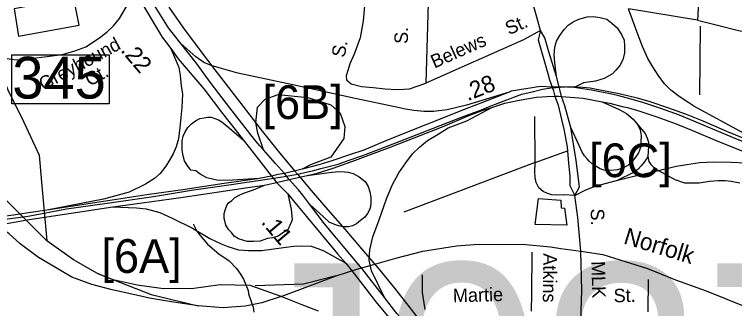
# Model space of a CAD drawing. Extents: x 1551653 to 1702041, y 811336 to 920032.
# Drawn here: x 1634519 to 1638018, y 854755 to 856187 of the extents above; entities that cross this region are included whole.
import ezdxf

# ---------------------------------------------------------------- set-up
doc = ezdxf.new("R2010")
doc.units = 0
for name, color, linetype in [('Old_Level_10', 7, 'Continuous'), ('Old_Level_11', 7, 'Continuous'), ('Old_Level_14', 7, 'Continuous'), ('Old_Level_17', 7, 'Continuous'), ('Old_Level_27', 7, 'Continuous'), ('Old_Level_28', 7, 'Continuous'), ('Old_Level_3', 7, 'Continuous'), ('Old_Level_31', 7, 'Continuous'), ('Old_Level_32', 7, 'Continuous'), ('Old_Level_35', 7, 'Continuous'), ('Old_Level_4', 7, 'Continuous'), ('Old_Level_41', 7, 'Continuous'), ('Old_Level_44', 7, 'Continuous'), ('Old_Level_47', 7, 'Continuous'), ('Old_Level_5', 7, 'Continuous'), ('Old_Level_50', 7, 'Continuous'), ('Old_Level_62', 7, 'Continuous')]:
    doc.layers.add(name, color=color, linetype=linetype)

msp = doc.modelspace()

# ---------------------------------------------------------------- linework, layer by layer
at = {"layer": 'Old_Level_27'}
for p, q in [((1637165.81, 855834.049), (1637132.268, 855832.239)), ((1637238.14, 855829.955), (1637165.81, 855834.049)), ((1635916.459, 855433.746), (1635831.443, 855412.301)), ((1635768.037, 855399.747), (1635708.82, 855387.841)), ((1635854.647, 855383.45), (1635942.198, 855402.482)), ((1635734.799, 855355.584), (1635793.039, 855369.066)), ((1635793.039, 855369.066), (1635854.647, 855383.45)), ((1634581.78, 855186.548), (1634996.937, 855249.62)), ((1634431.655, 855159.838), (1634581.78, 855186.548))]:
    msp.add_line(p, q, dxfattribs=at)
for points in [[(1637132.268, 855832.239), (1637075.639, 855836.199), (1636932.998, 855812.489), (1636922.245, 855808.742)], [(1638365.974, 855464.633), (1638214.741, 855507.081), (1638031.657, 855578.433), (1637750.359, 855695.757), (1637659.078, 855728.666), (1637571.765, 855757.86), (1637509.269, 855776.165), (1637455.868, 855789.561), (1637421.443, 855798.196), (1637322.164, 855817.451), (1637238.14, 855829.955)], [(1636922.245, 855808.742), (1636785.62, 855755.117), (1636716.75, 855727.875), (1636335.154, 855575.842), (1636216.613, 855525.784), (1636146.503, 855502.4), (1636061.359, 855474.024), (1635998.272, 855454.385), (1635916.459, 855433.746)], [(1636839.087, 855734.036), (1636902.275, 855755.117), (1636963.818, 855767.67), (1637008.634, 855775.143), (1637056.118, 855783.277), (1637105.735, 855787.6), (1637145.165, 855789.226)], [(1637145.165, 855789.226), (1637164.011, 855787.899), (1637177.001, 855787.67)], [(1637177.001, 855787.67), (1637283.064, 855778.84), (1637374.26, 855761.325)], [(1637374.26, 855761.325), (1637411.653, 855754.143), (1637471.911, 855739.026), (1637497.437, 855732.624), (1637558.267, 855714.807), (1637644.274, 855686.049), (1637734.161, 855653.643), (1637813.351, 855621.247), (1637928.857, 855572.058), (1638060.916, 855518.691), (1638279.006, 855441.845), (1638350.679, 855418.824)], [(1635942.198, 855402.482), (1635989.698, 855413.729), (1636066.967, 855438.954), (1636176.318, 855476.83), (1636249.219, 855504.885), (1636348.756, 855542.76), (1636602.803, 855640.615), (1636724.052, 855693.495), (1636792.102, 855719.441), (1636839.087, 855734.036)], [(1635831.443, 855412.301), (1635799.993, 855406.831), (1635768.037, 855399.747)], [(1635708.82, 855387.841), (1635700.182, 855386.291), (1635526.661, 855361.801), (1635348.615, 855335.148), (1635162.158, 855308.495), (1634910.501, 855269.501), (1634676.155, 855234.318)], [(1634996.937, 855249.62), (1635139.727, 855269.218), (1635327.586, 855295.87), (1635652.835, 855343.565), (1635734.799, 855355.584)], [(1634676.155, 855234.318), (1634587.23, 855220.967), (1634547.706, 855213.758)], [(1634547.706, 855213.758), (1634515.514, 855210.281), (1634403.045, 855195.464)]]:
    msp.add_lwpolyline(points, dxfattribs=at)
at = {"layer": 'Old_Level_28'}
for p, q in [((1635793.039, 855369.066), (1635846.931, 855313.314)), ((1636130.112, 854975.222), (1636159.335, 854936.7)), ((1636316.854, 854808.062), (1636208.296, 854948.192))]:
    msp.add_line(p, q, dxfattribs=at)
for points in [[(1635327.434, 856045.612), (1635267.763, 856121.124), (1635130.75, 856342.57)], [(1635106.73, 856298.457), (1635114.031, 856282.653), (1635237.133, 856076.332), (1635278.819, 856019.985)], [(1635278.819, 856019.985), (1635315.203, 855970.803), (1635439.02, 855824.439), (1635530.348, 855704.884), (1635591.277, 855626.938), (1635631.22, 855575.589)], [(1635729.063, 855527.112), (1635712.207, 855546.394), (1635684.985, 855577.536), (1635566.044, 855732.468), (1635475.699, 855850.735), (1635402.178, 855951.025), (1635327.434, 856045.612)], [(1635631.22, 855575.589), (1635661.057, 855537.231), (1635729.145, 855449.7), (1635768.037, 855399.747)], [(1635831.443, 855412.301), (1635786.833, 855461.024), (1635729.063, 855527.112)], [(1635768.037, 855399.747), (1635776.453, 855389.188), (1635793.039, 855369.066)], [(1635854.647, 855383.45), (1635842.095, 855398.273), (1635831.443, 855412.301)], [(1635954.152, 855261.07), (1635919.637, 855306.047), (1635899.9, 855333.433), (1635854.647, 855383.45)], [(1635846.931, 855313.314), (1635873.834, 855280.58), (1635930.361, 855213.229), (1636089.396, 855022.113), (1636130.112, 854975.222)], [(1636208.296, 854948.192), (1636026.474, 855166.828), (1635954.152, 855261.07)], [(1636159.335, 854936.7), (1636281.486, 854779.985), (1636372.807, 854670.288)], [(1636488.976, 854604.204), (1636376.318, 854731.305), (1636316.854, 854808.062)]]:
    msp.add_lwpolyline(points, dxfattribs=at)
at = {"layer": 'Old_Level_3'}
for points in [[(1635269.408, 856222.291), (1635341.291, 856119.16), (1635416.365, 856017.418), (1635493.277, 855916.758), (1635570.671, 855816.869), (1635647.193, 855717.443), (1635723.167, 855618.722), (1635801.104, 855521.492), (1635880.628, 855425.441), (1635894.273, 855409.331), (1635961.273, 855330.226), (1636042.573, 855235.506), (1636124.063, 855140.939), (1636205.275, 855046.18), (1636285.744, 854950.889), (1636365.005, 854854.723), (1636442.59, 854757.34), (1636517.461, 854657.592)], [(1636139.918, 855475.197), (1636206.355, 855498.983), (1636274.432, 855524.41), (1636381.059, 855565.42), (1636691.918, 855686.811), (1636787.883, 855721.26), (1636814.129, 855733.563), (1636898.611, 855766.371), (1636984.733, 855797.539), (1637034.765, 855809.022), (1637084.798, 855822.966), (1637124.988, 855828.707), (1637197.167, 855834.449), (1637217.672, 855836.089), (1637242.278, 855834.449), (1637280.828, 855832.808), (1637316.097, 855828.707), (1637330.861, 855826.247), (1637457.173, 855801.64), (1637544.115, 855780.315), (1637605.63, 855762.27), (1637692.572, 855732.743), (1637782.795, 855700.755), (1637863.176, 855667.946), (1637978.005, 855618.734), (1638110.058, 855565.42)], [(1634374.83, 855177.462), (1634586.443, 855205.349), (1634772.631, 855239.798), (1634969.481, 855268.505), (1635195.038, 855300.493), (1635379.585, 855330.841), (1635571.514, 855358.728), (1635747.858, 855384.974), (1635768.364, 855388.255), (1635830.699, 855397.278), (1635859.407, 855402.199), (1635894.273, 855409.331), (1635895.496, 855409.581), (1635943.888, 855420.243), (1635967.674, 855425.985), (1636007.864, 855436.648), (1636092.346, 855457.973), (1636139.918, 855475.197)]]:
    msp.add_lwpolyline(points, dxfattribs=at)
at = {"layer": 'Old_Level_31'}
for p, q in [((1635236.379, 856064.704), (1635236.379, 856064.704)), ((1637170.662, 855814.957), (1637170.662, 855814.957)), ((1637406.739, 855756.287), (1637406.739, 855756.287)), ((1636711.86, 855719.403), (1636711.86, 855719.403)), ((1635658.034, 855546.257), (1635658.034, 855546.257)), ((1635799.212, 855411.146), (1635799.212, 855411.146)), ((1635982.276, 855409.605), (1635982.276, 855409.605)), ((1635657.228, 855384.354), (1635657.228, 855384.354)), ((1635896.788, 855326.759), (1635896.788, 855326.759)), ((1634915.547, 855265.371), (1634915.547, 855265.371)), ((1637261.021, 855085.799), (1637261.021, 855085.799)), ((1636091.628, 855020.996), (1636091.628, 855020.996)), ((1636183.15, 854947.271), (1636183.15, 854947.271))]:
    msp.add_line(p, q, dxfattribs=at)
msp.add_lwpolyline([(1634507.09, 855988.961), (1634978.784, 855988.961), (1634978.784, 855751.129), (1634507.09, 855751.129), (1634507.09, 855988.961)], dxfattribs=at)
at = {"layer": 'Old_Level_32'}
msp.add_line((1637165.81, 855834.049), (1637152.766, 855884.451), dxfattribs=at)
for points in [[(1637074.919, 856108.685), (1637049.522, 856202.339), (1636998.205, 856369.887), (1636978.763, 856485.245), (1636973.698, 856534.935), (1636977.338, 856834.642), (1636989.811, 857125.822), (1637000.891, 857362.79), (1637000.891, 857628.252), (1637007.809, 858026.779), (1637004.295, 858375)], [(1637074.919, 856108.685), (1637064.412, 856062.106), (1637109.851, 855899.603), (1637119.107, 855868.45), (1637132.268, 855832.239)], [(1637152.766, 855884.451), (1637114.79, 856003.59), (1637096.737, 856073.082), (1637074.919, 856108.685)], [(1637132.268, 855832.239), (1637137.65, 855814.821), (1637145.165, 855789.226)], [(1637177.001, 855787.67), (1637170.661, 855814.956), (1637165.81, 855834.049)], [(1637145.165, 855789.226), (1637160.675, 855744.547), (1637177.293, 855674.337), (1637188.371, 855628.147), (1637204.991, 855541.309), (1637210.529, 855461.862), (1637216.962, 855400.065), (1637216.962, 855353.152), (1637242.208, 855304.435)], [(1637223.046, 855636.22), (1637192.541, 855741.823), (1637177.001, 855787.67)], [(1637242.208, 855304.435), (1637264.302, 855346.801), (1637248.925, 855475.055), (1637223.046, 855636.22)], [(1637270.601, 855034.367), (1637256.614, 855198.027), (1637242.208, 855304.435)], [(1637255.907, 854057.878), (1637266.377, 854244.075), (1637268.664, 854395.172), (1637268.664, 854543.98), (1637272.848, 854742.479), (1637276.135, 854843.52), (1637270.601, 855034.367)]]:
    msp.add_lwpolyline(points, dxfattribs=at)
at = {"layer": 'Old_Level_35'}
for p, q in [((1636528.839, 856242.416), (1636518.602, 855851.68)), ((1637837.634, 856158.424), (1637502.575, 856213.111)), ((1637850.557, 856129.745), (1637847.374, 855795.832)), ((1637049.447, 855464.993), (1637047.334, 855689.104)), ((1637049.447, 855464.993), (1637206.309, 855522.401)), ((1637049.447, 855464.993), (1636411.332, 855223.97)), ((1637597.498, 854739.525), (1637600.424, 854895.649))]:
    msp.add_line(p, q, dxfattribs=at)
for points in [[(1637875.148, 857083.62), (1637862.988, 856623.56), (1637837.634, 856158.424)], [(1634484.654, 855971.104), (1634503.836, 855967.905), (1634529.413, 855965.346), (1634566.482, 855968.668), (1634623.471, 855975.796), (1634679.033, 855981.98), (1634713.562, 855986.459), (1634741.009, 855990.052), (1634768.316, 855995.992), (1634813.432, 856009.059), (1634866.859, 856029.255), (1634927.409, 856068.459), (1634968.963, 856099.346), (1635001.019, 856131.421), (1635029.513, 856167.061), (1635106.623, 856298.292)], [(1636221.705, 856245.343), (1636212.93, 856154.61), (1636198.304, 856072.658), (1636170.516, 855993.633), (1636148.578, 855945.339), (1636139.802, 855913.144), (1636131.027, 855886.803), (1636132.489, 855867.778), (1636155.89, 855848.753), (1636205.617, 855835.582), (1636262.837, 855830.225), (1636320.737, 855823.847), (1636376.711, 855821.107), (1636410.563, 855822.823), (1636438.617, 855824.654), (1636518.602, 855851.68)], [(1637837.634, 856158.424), (1637935.062, 856134.646), (1638037.243, 856108.491), (1638096.65, 856096.602), (1638169.851, 856076.835)], [(1637074.919, 856108.685), (1636992.34, 856062.537), (1636518.602, 855851.68)], [(1637242.208, 855304.435), (1637188.902, 855308.54), (1637152.982, 855306.426), (1637129.74, 855308.54), (1637108.609, 855314.883), (1637087.48, 855325.454), (1637066.351, 855342.368), (1637053.673, 855367.739), (1637049.447, 855393.109), (1637047.334, 855418.48), (1637049.447, 855464.993)], [(1637647.853, 855426.164), (1637727.948, 855382.936), (1637774.132, 855366.132), (1637803.522, 855366.132), (1637845.508, 855366.132), (1637895.891, 855374.534), (1637937.877, 855378.735), (1637971.465, 855378.735), (1638000.855, 855374.534), (1638042.841, 855366.132)], [(1637031.846, 854743.129), (1637033.455, 854826.037), (1637035.181, 855029.311)], [(1636514.077, 854750.392), (1636501.98, 854832.704), (1636501.98, 854919.858)]]:
    msp.add_lwpolyline(points, dxfattribs=at)
at = {"layer": 'Old_Level_41'}
msp.add_lwpolyline([(1634539.926, 856080.879), (1634833.906, 856133.688), (1634803.754, 856290.233), (1634726.49, 856275.144), (1634730.857, 856252.82), (1634517.312, 856212.903), (1634539.926, 856080.879)], dxfattribs=at)
at = {"layer": 'Old_Level_44'}
msp.add_line((1635814.836, 854813.225), (1636081.583, 854914.876), dxfattribs=at)
for points in [[(1634074.777, 856642.693), (1634134.892, 856548.155), (1634229.049, 856335.555), (1634305.605, 856156.097), (1634359.826, 856064.843), (1634440.745, 855932.638), (1634488.077, 855819.257), (1634565.693, 855662.271), (1634640.207, 855500.739), (1634650.603, 855369.678), (1634677.333, 855085.134)], [(1634677.333, 855085.134), (1634460.473, 855301.891), (1634386.519, 855398.461), (1634268.586, 855603.117), (1634125.969, 855861.845), (1633979.268, 856111.253), (1633880.128, 856260.803), (1633850.178, 856379.586), (1633821.322, 856520.208)], [(1637202.324, 855160.827), (1637048.325, 855164.758), (1637065.887, 855290.469), (1637173.794, 855283.071), (1637175.424, 855245.22), (1637191.386, 855242.894), (1637202.324, 855160.827)], [(1635640.22, 854766.573), (1635533.577, 854759.04), (1635412.406, 854767.787), (1635281.887, 854787.813), (1635176.181, 854805.168), (1635105.024, 854821.776), (1634994.751, 854846.579), (1634895.637, 854871.691), (1634798.021, 854908.439), (1634710.81, 854959.436), (1634637.052, 855003.831), (1634547.974, 855070.375), (1634492.771, 855120.598), (1634431.655, 855159.838)], [(1635814.836, 854813.225), (1635663.954, 854866.513), (1635518.725, 854870.528), (1635379.463, 854851.695), (1635232.547, 854852.074), (1635116.414, 854868.387), (1634999.772, 854894.57), (1634922.858, 854925.484), (1634805.531, 854991.605), (1634677.333, 855085.134)], [(1636081.583, 854914.876), (1636183.149, 854947.271), (1636259.043, 854968.495), (1636371.769, 855000.889), (1636503.469, 855034.4), (1636667.659, 855061.059), (1636773.908, 855068.655), (1636870.127, 855065.949), (1636985.993, 855068.13), (1637123.614, 855055.728), (1637174.262, 855047.413), (1637270.601, 855034.367), (1637378.331, 855018.828), (1637594.986, 854950.126), (1637730.127, 854894.306), (1637880.284, 854840.633), (1638189.888, 854716.983)], [(1634922.858, 854925.484), (1635183.649, 854823.525), (1635412.406, 854767.787)], [(1636081.583, 854914.876), (1635923.815, 854874.158), (1635689.465, 854865.564)], [(1635814.836, 854813.225), (1635721.973, 854782.639), (1635640.22, 854766.573)], [(1635997.194, 854741.634), (1635913.112, 854775.259), (1635814.836, 854813.225)]]:
    msp.add_lwpolyline(points, dxfattribs=at)
at = {"layer": 'Old_Level_47'}
for points in [[(1638365.974, 855464.633), (1638064.625, 855606.602), (1637819.735, 855740.486), (1637794.953, 855756.675), (1637749.337, 855786.616), (1637708.539, 855817.462), (1637677.972, 855849.299), (1637646.414, 855891.563), (1637620.813, 855931.704), (1637597.221, 855972.006), (1637569.786, 856030.195), (1637544.36, 856098.547), (1637502.575, 856213.111)], [(1637152.766, 855884.451), (1637144.003, 855952.827), (1637141.88, 855988.954), (1637144.003, 856027.205), (1637152.499, 856056.956), (1637169.489, 856084.583), (1637190.727, 856112.208), (1637209.841, 856133.46), (1637233.203, 856150.46), (1637260.812, 856163.21), (1637301.165, 856173.836), (1637330.897, 856175.961), (1637364.879, 856171.711), (1637396.736, 856163.21), (1637422.221, 856144.085), (1637447.707, 856120.709), (1637468.856, 856088.966)], [(1637468.856, 856088.966), (1637468.945, 856088.832), (1637481.688, 856061.207), (1637483.811, 856031.455), (1637483.811, 855999.579), (1637475.316, 855965.577), (1637460.449, 855937.952), (1637441.335, 855914.576), (1637424.345, 855897.574), (1637383.993, 855874.198), (1637341.517, 855861.448), (1637284.174, 855852.948), (1637238.14, 855829.955)], [(1635278.819, 856019.985), (1635301.896, 855966.876), (1635317.856, 855928.09), (1635324.697, 855889.304), (1635329.257, 855839.11), (1635335.215, 855797.666), (1635331.974, 855732.8), (1635322.899, 855635.806), (1635316.059, 855581.049), (1635304.528, 855542.497), (1635290.847, 855508.275), (1635272.821, 855477.465), (1635254.58, 855447.805), (1635226.66, 855411.717), (1635200.168, 855387.199), (1635156.846, 855359.821), (1635077.546, 855321.626), (1634952.137, 855287.403), (1634676.155, 855234.318)], [(1636922.245, 855808.742), (1636715.951, 855745.387), (1636622.104, 855722.752), (1636555.979, 855713.625), (1636508.096, 855713.625), (1636460.213, 855718.189), (1636419.169, 855725.034), (1636366.726, 855736.441), (1636175.194, 855777.509), (1635871.933, 855843.673), (1635605.155, 855900.712), (1635513.95, 855925.808), (1635475.187, 855937.216), (1635438.705, 855953.187), (1635399.942, 855980.565), (1635327.434, 856045.612)], [(1635729.063, 855527.112), (1635702.11, 855607.91), (1635691.96, 855658.456), (1635699.547, 855734.274), (1635737.481, 855774.72), (1635800.637, 855797.481), (1635944.686, 855782.307), (1636055.927, 855746.936), (1636101.346, 855706.49), (1636124.107, 855640.77), (1636119.083, 855582.638), (1636055.927, 855491.697), (1635957.297, 855453.763), (1635916.459, 855433.746)], [(1637374.26, 855761.325), (1637457.35, 855723.35), (1637493.35, 855703.838), (1637524.851, 855676.821), (1637547.312, 855649.853)], [(1636316.854, 854808.062), (1636254.315, 854937.904), (1636242.914, 854990.38), (1636245.194, 855040.573), (1636261.155, 855104.456), (1636290.798, 855186.591), (1636327.28, 855289.26), (1636354.642, 855355.425), (1636386.564, 855414.745), (1636420.766, 855464.938), (1636452.688, 855508.288), (1636486.891, 855540.229), (1636525.653, 855572.171), (1636578.096, 855604.112), (1636625.98, 855633.772), (1636717.572, 855669.171), (1636839.087, 855734.036)], [(1635708.82, 855387.841), (1635578.432, 855380.059), (1635509.26, 855378.905), (1635453.892, 855391.617), (1635421.643, 855408.906), (1635400.891, 855425.06), (1635376.857, 855428.676), (1635359.079, 855452.394), (1635345.746, 855473.147), (1635338.339, 855498.347), (1635333.894, 855525.029), (1635333.894, 855554.676), (1635333.894, 855570.982), (1635339.82, 855593.217), (1635348.709, 855615.452), (1635362.042, 855636.205), (1635379.819, 855653.994), (1635399.078, 855668.817), (1635419.819, 855679.194), (1635440.559, 855683.641), (1635456.855, 855686.605), (1635474.632, 855686.605), (1635492.409, 855680.676), (1635510.187, 855673.265), (1635526.483, 855662.888), (1635553.149, 855642.135), (1635631.22, 855575.589)], [(1637547.312, 855649.853), (1637559.352, 855624.288), (1637563.852, 855595.77), (1637562.352, 855567.253), (1637560.852, 855538.735), (1637551.852, 855513.219), (1637536.852, 855492.205), (1637520.351, 855471.192), (1637499.351, 855451.68), (1637476.85, 855439.672), (1637449.85, 855430.667), (1637415.349, 855427.665), (1637383.848, 855429.166), (1637364.348, 855435.17), (1637340.348, 855450.179), (1637325.348, 855459.184), (1637311.847, 855472.693), (1637301.347, 855483.2), (1637289.346, 855498.209), (1637275.847, 855519.222), (1637262.346, 855547.74), (1637223.046, 855636.22)], [(1637547.312, 855649.853), (1637583.353, 855606.276), (1637593.852, 855583.763), (1637599.853, 855564.251), (1637599.853, 855543.237), (1637596.392, 855494.767)], [(1637596.392, 855494.767), (1637589.352, 855483.2), (1637578.852, 855466.689), (1637563.852, 855450.179), (1637547.351, 855432.168), (1637523.351, 855415.658), (1637450.444, 855379.182)], [(1637596.392, 855494.767), (1637601.353, 855471.192), (1637610.353, 855456.183), (1637629.853, 855436.671), (1637647.853, 855426.164)], [(1637647.853, 855426.164), (1637733.355, 855447.177), (1637785.856, 855456.183), (1637848.857, 855465.188), (1637913.359, 855469.691), (1638001.86, 855468.19), (1638073.861, 855463.687), (1638129.362, 855454.682), (1638202.863, 855438.172), (1638265.864, 855426.164), (1638350.679, 855418.824)], [(1637450.444, 855379.182), (1637521.851, 855397.647), (1637647.853, 855426.164)], [(1635942.198, 855402.482), (1636049.086, 855416.475), (1636094.469, 855421.817), (1636122.5, 855420.482), (1636141.188, 855419.147), (1636165.214, 855412.469), (1636194.579, 855396.441), (1636222.611, 855373.736), (1636237.293, 855348.359), (1636245.302, 855322.982), (1636250.641, 855297.606), (1636250.641, 855270.893), (1636249.307, 855250.86), (1636243.967, 855234.832), (1636234.623, 855217.469), (1636221.275, 855200.106), (1636201.253, 855182.743), (1636181.231, 855166.716), (1636161.21, 855157.367), (1636142.522, 855153.36), (1636117.161, 855152.024), (1636093.134, 855157.367), (1636071.778, 855165.38), (1636049.086, 855176.065), (1636018.385, 855202.777), (1635954.152, 855261.07)], [(1635846.931, 855313.314), (1635853.523, 855282.165), (1635863.892, 855239.177), (1635867.8, 855186.208), (1635861.366, 855170.025), (1635848.033, 855138.896), (1635823.992, 855123.899), (1635800.934, 855107.745), (1635773.574, 855098.45), (1635749.009, 855095.252), (1635713.146, 855083.289), (1635680.555, 855081.806), (1635649.444, 855081.806), (1635629.158, 855088.129), (1635608.407, 855093.898), (1635586.502, 855107.745), (1635573.412, 855124.484), (1635560.079, 855139.307), (1635546.729, 855160.101), (1635540.803, 855182.336), (1635538.082, 855193.479), (1635538.082, 855217.197), (1635545.132, 855238.536), (1635551.058, 855256.324), (1635559.986, 855269.287), (1635574.973, 855280.825), (1635587.655, 855293.518), (1635614.17, 855308.519), (1635637.228, 855318.903), (1635681.037, 855332.75), (1635734.799, 855355.584)], [(1637242.208, 855304.435), (1637292.347, 855331.605), (1637335.847, 855349.616), (1637388.349, 855363.125), (1637450.444, 855379.182)], [(1634996.937, 855249.62), (1635111.588, 855244.738), (1635158.679, 855240.25), (1635225.952, 855222.3), (1635288.739, 855193.131), (1635385.163, 855146.012), (1635468.132, 855096.649), (1635524.193, 855069.723), (1635555.586, 855056.261), (1635607.162, 855040.554), (1635656.495, 855038.311), (1635721.525, 855038.311), (1635779.828, 855045.042), (1635826.918, 855051.773), (1635876.251, 855058.504), (1635914.372, 855060.749), (1635961.464, 855058.504), (1635992.857, 855047.286), (1636022.008, 855036.067), (1636130.112, 854975.222)]]:
    msp.add_lwpolyline(points, dxfattribs=at)
at = {"layer": 'Old_Level_50'}
for p, q in [((1637157.669, 855805.036), (1637157.669, 855805.036)), ((1635803.428, 855395.896), (1635803.428, 855395.896)), ((1637262.66, 855030.115), (1637262.66, 855030.115)), ((1636183.15, 854947.272), (1636183.15, 854947.272))]:
    msp.add_line(p, q, dxfattribs=at)
at = {"layer": 'Old_Level_62'}
msp.add_lwpolyline([(1635389.146, 855165.612), (1635389.815, 855164.075), (1635405.604, 855131.984), (1635421.393, 855109.839), (1635457.072, 855067.598), (1635512.642, 855021.205), (1635562.367, 854986.808), (1635598.046, 854950.565), (1635617.833, 854922.421), (1635631.674, 854898.328), (1635655.255, 854842.195), (1635657.203, 854826.149), (1635678.734, 854762.02), (1635682.527, 854738.029)], dxfattribs=at)

# ---------------------------------------------------------------- texts
at = {"layer": 'Old_Level_10'}
for s, rotation, p in [('St.', 24.057953, (1636921.71, 856084.566)), ('S.', 88.892828, (1636430.466, 856042.485)), ('Greyhound', 28.607333, (1634660.351, 855812.992)), ('Belews', 24.057953, (1636559.789, 855922.655)), ('S.', 79.486875, (1636123.635, 855973.808)), ('Ct.', 28.607333, (1634884.811, 855834.453)), ('Atkins', 269.155258, (1637089.573, 855024.07)), ('Martie', 1.581364, (1636650.256, 854785.203)), ('St.', 1.658839, (1637431.031, 854784.943))]:
    msp.add_text(s, height=65.6167, rotation=rotation, dxfattribs=at).set_placement(p)
at = {"layer": 'Old_Level_11'}
for s, rotation, p in [('S.', 270.353169, (1637319.186, 855241.852)), ('MLK', 271.585744, (1637321.953, 854985.111))]:
    msp.add_text(s, height=65.6167, rotation=rotation, dxfattribs=at).set_placement(p)
at = {"layer": 'Old_Level_14'}
msp.add_text('Norfolk', height=82.0208, rotation=343.083531, dxfattribs=at).set_placement((1637474.195, 855072.337))
at = {"layer": 'Old_Level_17'}
for s, rotation, p in [('.22', 310.229347, (1635032.214, 856010.164)), ('.28', 21.485683, (1636721.313, 855763.883)), ('.11', 310.00555, (1635714.938, 855173.658))]:
    msp.add_text(s, height=82.0208, rotation=rotation, dxfattribs=at).set_placement(p)
at = {"layer": 'Old_Level_31'}
msp.add_text('345', height=203.4117, dxfattribs=at).set_placement((1634509.066, 855776.928))
at = {"layer": 'Old_Level_4'}
msp.add_text('J0372', height=1049.8646, dxfattribs=at).set_placement((1635597.943, 853924.638))
at = {"layer": 'Old_Level_5'}
for s, p in [('[6B]', (1635724.284, 855677.311)), ('[6C]', (1637310.545, 855394.505)), ('[6A]', (1634941.838, 854928.596))]:
    msp.add_text(s, height=164.0417, dxfattribs=at).set_placement(p)

doc.saveas('drawing.dxf')
